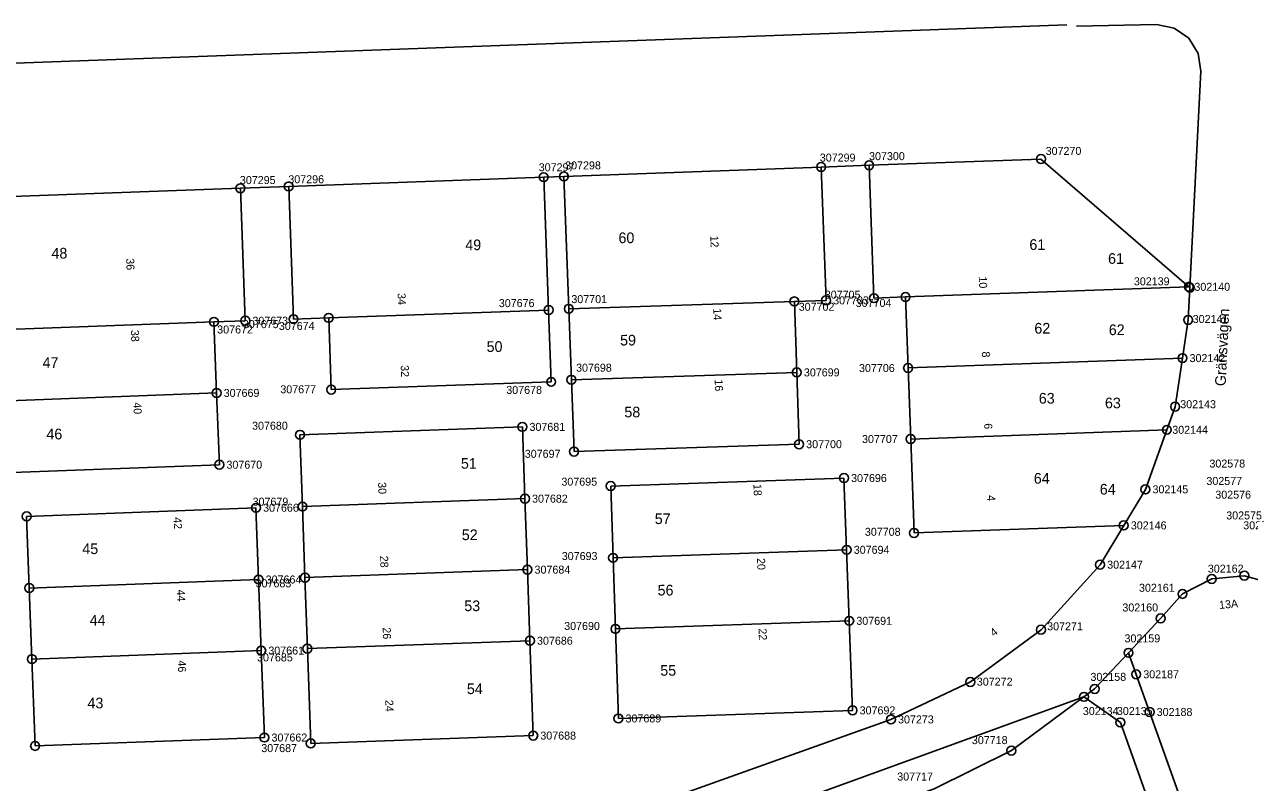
# Model space of a CAD drawing. Extents: x 141995 to 152570, y 6580184 to 6586000.
# Drawn here: x 142748 to 142885.7, y 6585280.8 to 6585366.1 of the extents above; entities that cross this region are included whole.
import ezdxf

# ---------------------------------------------------------------- set-up
doc = ezdxf.new("R2010")
doc.units = 0
for name, color, linetype in [('Level 10', 7, 'Continuous'), ('Level 13', 7, 'Continuous'), ('Level 42', 7, 'Continuous'), ('Level 5', 7, 'Continuous'), ('Level 51', 7, 'Continuous'), ('Level 53', 7, 'Continuous'), ('Level 54', 7, 'Continuous'), ('Level 55', 7, 'Continuous'), ('Level 59', 7, 'Continuous'), ('Level 6', 7, 'Continuous'), ('Level 7', 7, 'Continuous')]:
    doc.layers.add(name, color=color, linetype=linetype)

msp = doc.modelspace()

# ---------------------------------------------------------------- linework, layer by layer
at = {"layer": 'Level 10'}
for centre in [(142837.55, 6585350.09), (142842.95, 6585350.29), (142862.27, 6585350.99), (142806.35, 6585348.95), (142808.62, 6585349.03), (142772.24, 6585347.7), (142777.67, 6585347.9), (142878.9, 6585336.61), (142879.02, 6585336.51), (142834.54, 6585334.96), (142838.1, 6585335.08), (142843.49, 6585335.33), (142847.04, 6585335.46), (142806.9, 6585333.99), (142809.17, 6585334.13), (142769.26, 6585332.66), (142772.79, 6585332.79), (142778.21, 6585332.97), (142782.17, 6585333.11), (142878.83, 6585332.88), (142878.19, 6585328.58), (142834.81, 6585326.97), (142847.33, 6585327.47), (142807.19, 6585325.91), (142809.46, 6585326.14), (142769.56, 6585324.66), (142782.45, 6585325.03), (142877.36, 6585323.11), (142778.94, 6585319.95), (142803.95, 6585320.84), (142876.43, 6585320.51), (142835.07, 6585318.88), (142847.62, 6585319.47), (142809.76, 6585318.06), (142769.87, 6585316.58), (142840.12, 6585315.08), (142813.88, 6585314.18), (142874.02, 6585313.8), (142773.99, 6585311.73), (142779.22, 6585311.87), (142804.24, 6585312.76), (142748.2, 6585310.77), (142848, 6585308.9), (142871.58, 6585309.75), (142814.15, 6585306.1), (142840.42, 6585307), (142804.52, 6585304.77), (142868.92, 6585305.33), (142774.28, 6585303.66), (142779.5, 6585303.87), (142881.48, 6585303.72), (142885.15, 6585304.09), (142748.49, 6585302.7), (142878.19, 6585302.04), (142875.73, 6585299.28), (142814.42, 6585298.1), (142840.71, 6585299.01), (142862.28, 6585298.01), (142804.8, 6585296.77), (142774.58, 6585295.66), (142779.77, 6585295.88), (142872.12, 6585295.41), (142748.79, 6585294.7), (142872.98, 6585292.98), (142854.33, 6585292.13), (142868.31, 6585291.34), (142867.11, 6585290.45), (142841.08, 6585288.93), (142874.49, 6585288.75), (142814.75, 6585288.02), (142845.4, 6585287.91), (142871.2, 6585287.57), (142774.94, 6585285.87), (142805.17, 6585286.09), (142749.15, 6585284.93), (142780.15, 6585285.21), (142858.95, 6585284.4)]:
    msp.add_circle(centre, 0.5, dxfattribs=at)
at = {"layer": 'Level 13'}
for points in [[(142615.3, 6585356.97), (142865.18, 6585366.11)], [(142875.25, 6585366.13), (142866.26, 6585365.96)], [(142877.27, 6585365.72), (142875.25, 6585366.13)], [(142878.89, 6585364.58), (142877.27, 6585365.72)], [(142879.96, 6585362.86), (142878.89, 6585364.58)], [(142880.27, 6585360.89), (142879.96, 6585362.86)], [(142879.02, 6585336.51), (142880.27, 6585360.89)]]:
    msp.add_lwpolyline(points, dxfattribs=at)
at = {"layer": 'Level 5'}
for points in [[(142842.95, 6585350.29), (142862.27, 6585350.99)], [(142862.27, 6585350.99), (142878.9, 6585336.61)], [(142808.62, 6585349.03), (142837.55, 6585350.09)], [(142837.55, 6585350.09), (142842.95, 6585350.29)], [(142772.24, 6585347.7), (142777.67, 6585347.9)], [(142777.67, 6585347.9), (142806.35, 6585348.95)], [(142806.35, 6585348.95), (142808.62, 6585349.03)], [(142742.4, 6585346.61), (142772.24, 6585347.7)], [(142879.02, 6585336.51), (142878.83, 6585332.88)], [(142878.9, 6585336.61), (142879.02, 6585336.51)], [(142878.83, 6585332.88), (142878.19, 6585328.58)], [(142878.19, 6585328.58), (142877.36, 6585323.11)], [(142877.36, 6585323.11), (142876.43, 6585320.51)], [(142876.43, 6585320.51), (142874.02, 6585313.8)], [(142874.02, 6585313.8), (142871.58, 6585309.75)], [(142871.58, 6585309.75), (142868.92, 6585305.33)], [(142862.28, 6585298.01), (142868.92, 6585305.33)], [(142878.19, 6585302.04), (142881.48, 6585303.72)], [(142881.48, 6585303.72), (142885.15, 6585304.09)], [(142885.15, 6585304.09), (142888.7, 6585303.11)], [(142875.73, 6585299.28), (142878.19, 6585302.04)], [(142872.12, 6585295.41), (142875.73, 6585299.28)], [(142862.28, 6585298.01), (142854.33, 6585292.13)], [(142868.31, 6585291.34), (142872.12, 6585295.41)], [(142854.33, 6585292.13), (142845.4, 6585287.91)], [(142867.11, 6585290.45), (142868.31, 6585291.34)], [(142788.63, 6585261.93), (142867.11, 6585290.45)], [(142858.95, 6585284.4), (142867.11, 6585290.45)], [(142845.4, 6585287.91), (142630.63, 6585211.17)], [(142850.27, 6585280.1), (142858.95, 6585284.4)]]:
    msp.add_lwpolyline(points, dxfattribs=at)
at = {"layer": 'Level 6'}
for points in [[(142630.63, 6585211.17), (142845.4, 6585287.91), (142854.33, 6585292.13), (142862.28, 6585298.01), (142868.92, 6585305.33), (142871.58, 6585309.75), (142874.02, 6585313.8), (142876.43, 6585320.51), (142877.36, 6585323.11), (142878.19, 6585328.58), (142878.83, 6585332.88), (142879.02, 6585336.51), (142878.9, 6585336.61), (142862.27, 6585350.99), (142842.95, 6585350.29), (142837.55, 6585350.09), (142808.62, 6585349.03), (142806.35, 6585348.95), (142777.67, 6585347.9), (142772.24, 6585347.7), (142742.4, 6585346.61)], [(142888.7, 6585303.11), (142885.15, 6585304.09), (142881.48, 6585303.72), (142878.19, 6585302.04), (142875.73, 6585299.28), (142872.12, 6585295.41), (142868.31, 6585291.34), (142867.11, 6585290.45), (142858.95, 6585284.4), (142850.27, 6585280.1), (142826.03, 6585271.43), (142822.74, 6585270.26), (142801.83, 6585262.78), (142783.27, 6585256.15), (142780.72, 6585254.66), (142778.89, 6585252.36), (142778.01, 6585249.55), (142778.21, 6585246.61), (142785.15, 6585219.83)]]:
    msp.add_lwpolyline(points, dxfattribs=at)
at = {"layer": 'Level 7'}
for points in [[(142837.55, 6585350.09), (142838.1, 6585335.08)], [(142843.49, 6585335.33), (142842.95, 6585350.29)], [(142778.21, 6585332.97), (142777.67, 6585347.9)], [(142806.35, 6585348.95), (142806.9, 6585333.99)], [(142809.17, 6585334.13), (142808.62, 6585349.03)], [(142772.24, 6585347.7), (142772.79, 6585332.79)], [(142847.04, 6585335.46), (142843.49, 6585335.33)], [(142847.04, 6585335.46), (142878.9, 6585336.61)], [(142847.33, 6585327.47), (142847.04, 6585335.46)], [(142809.17, 6585334.13), (142834.54, 6585334.96)], [(142809.46, 6585326.14), (142809.17, 6585334.13)], [(142838.1, 6585335.08), (142834.54, 6585334.96)], [(142834.54, 6585334.96), (142834.81, 6585326.97)], [(142742.95, 6585331.67), (142769.26, 6585332.66)], [(142772.79, 6585332.79), (142769.26, 6585332.66)], [(142769.26, 6585332.66), (142769.56, 6585324.66)], [(142782.17, 6585333.11), (142778.21, 6585332.97)], [(142806.9, 6585333.99), (142782.17, 6585333.11)], [(142782.45, 6585325.03), (142782.17, 6585333.11)], [(142806.9, 6585333.99), (142807.19, 6585325.91)], [(142847.33, 6585327.47), (142878.19, 6585328.58)], [(142847.62, 6585319.47), (142847.33, 6585327.47)], [(142807.19, 6585325.91), (142782.45, 6585325.03)], [(142809.46, 6585326.14), (142834.81, 6585326.97)], [(142809.76, 6585318.06), (142809.46, 6585326.14)], [(142834.81, 6585326.97), (142835.07, 6585318.88)], [(142743.24, 6585323.67), (142769.56, 6585324.66)], [(142769.56, 6585324.66), (142769.87, 6585316.58)], [(142778.94, 6585319.95), (142803.95, 6585320.84)], [(142803.95, 6585320.84), (142804.24, 6585312.76)], [(142847.62, 6585319.47), (142876.43, 6585320.51)], [(142779.22, 6585311.87), (142778.94, 6585319.95)], [(142835.07, 6585318.88), (142809.76, 6585318.06)], [(142848, 6585308.9), (142847.62, 6585319.47)], [(142769.87, 6585316.58), (142743.54, 6585315.59)], [(142813.88, 6585314.18), (142840.12, 6585315.08)], [(142840.12, 6585315.08), (142840.42, 6585307)], [(142814.15, 6585306.1), (142813.88, 6585314.18)], [(142804.24, 6585312.76), (142779.22, 6585311.87)], [(142804.24, 6585312.76), (142804.52, 6585304.77)], [(142748.2, 6585310.77), (142773.99, 6585311.73)], [(142748.49, 6585302.7), (142748.2, 6585310.77)], [(142773.99, 6585311.73), (142774.28, 6585303.66)], [(142779.5, 6585303.87), (142779.22, 6585311.87)], [(142848, 6585308.9), (142871.58, 6585309.75)], [(142814.15, 6585306.1), (142840.42, 6585307)], [(142840.42, 6585307), (142840.71, 6585299.01)], [(142814.42, 6585298.1), (142814.15, 6585306.1)], [(142804.52, 6585304.77), (142779.5, 6585303.87)], [(142779.77, 6585295.88), (142779.5, 6585303.87)], [(142804.52, 6585304.77), (142804.8, 6585296.77)], [(142748.49, 6585302.7), (142774.28, 6585303.66)], [(142748.79, 6585294.7), (142748.49, 6585302.7)], [(142774.28, 6585303.66), (142774.58, 6585295.66)], [(142814.42, 6585298.1), (142840.71, 6585299.01)], [(142840.71, 6585299.01), (142841.08, 6585288.93)], [(142814.75, 6585288.02), (142814.42, 6585298.1)], [(142748.79, 6585294.7), (142774.58, 6585295.66)], [(142774.58, 6585295.66), (142774.94, 6585285.87)], [(142804.8, 6585296.77), (142779.77, 6585295.88)], [(142780.15, 6585285.21), (142779.77, 6585295.88)], [(142804.8, 6585296.77), (142805.17, 6585286.09)], [(142749.15, 6585284.93), (142748.79, 6585294.7)], [(142872.12, 6585295.41), (142872.98, 6585292.98)], [(142872.98, 6585292.98), (142874.49, 6585288.75)], [(142867.11, 6585290.45), (142871.2, 6585287.57)], [(142841.08, 6585288.93), (142814.75, 6585288.02)], [(142874.49, 6585288.75), (142883.23, 6585264.26)], [(142871.2, 6585287.57), (142880.89, 6585260.38)], [(142774.94, 6585285.87), (142749.15, 6585284.93)], [(142805.17, 6585286.09), (142780.15, 6585285.21)]]:
    msp.add_lwpolyline(points, dxfattribs=at)

# ---------------------------------------------------------------- texts
at = {"layer": 'Level 42'}
msp.add_text('Gränsvägen', height=1.2, rotation=87.285, dxfattribs=at).set_placement((142883.04, 6585325.4))
at = {"layer": 'Level 51'}
for s, rotation, p in [('60', 0.0493, (142814.76, 6585341.52)), ('48', 0.0493, (142750.99, 6585339.79)), ('49', 0.0493, (142797.53, 6585340.73)), ('61', 0.0493, (142860.97, 6585340.76)), ('62', 0.0493, (142861.53, 6585331.34)), ('50', 0.0493, (142799.93, 6585329.28)), ('59', 0.0493, (142814.94, 6585330)), ('47', 0.0493, (142749.99, 6585327.47)), ('63', 0.0493, (142862.03, 6585323.46)), ('58', 0.0493, (142815.42, 6585321.91)), ('46', 0.0493, (142750.42, 6585319.43)), ('51', 0.0493, (142797.04, 6585316.13)), ('64', 0.0493, (142861.47, 6585314.45)), ('57', 0.0493, (142818.84, 6585309.9)), ('52', 0.0493, (142797.14, 6585308.09)), ('45', 0.0493, (142754.46, 6585306.52)), ('56', 0.0493, (142819.16, 6585301.86)), ('53', 0.0493, (142797.42, 6585300.1)), ('44', 0.0493, (142755.29, 6585298.48)), ('55', 0.0493, (142819.46, 6585292.83)), ('54', 0.0493, (142797.71, 6585290.76)), ('43', 0.0514, (142755.04, 6585289.16))]:
    msp.add_text(s, height=1.2, rotation=rotation, dxfattribs=at).set_placement(p)
at = {"layer": 'Level 53'}
for s, p in [('307270', (142862.8, 6585351.45)), ('307298', (142808.76, 6585349.82)), ('307299', (142837.4, 6585350.7)), ('307300', (142842.94, 6585350.86)), ('307296', (142777.63, 6585348.26)), ('307297', (142805.79, 6585349.61)), ('307295', (142772.18, 6585348.17)), ('302139', (142872.72, 6585336.77)), ('302140', (142879.53, 6585336.16)), ('307701', (142809.46, 6585334.77)), ('307705', (142837.96, 6585335.27)), ('307703', (142838.9, 6585334.63)), ('307676', (142801.3, 6585334.32)), ('307702', (142835.03, 6585333.91)), ('307704', (142841.44, 6585334.34)), ('307675', (142772.52, 6585331.95)), ('307673', (142773.59, 6585332.34)), ('307674', (142776.56, 6585331.75)), ('302141', (142879.34, 6585332.53)), ('307672', (142769.63, 6585331.35)), ('302142', (142878.99, 6585328.13)), ('307698', (142809.99, 6585327.05)), ('307699', (142835.61, 6585326.52)), ('307706', (142841.81, 6585327.01)), ('307669', (142770.36, 6585324.21)), ('307677', (142776.73, 6585324.62)), ('307678', (142802.14, 6585324.55)), ('302143', (142877.94, 6585322.94)), ('307680', (142773.55, 6585320.52)), ('307681', (142804.75, 6585320.39)), ('302144', (142877.04, 6585320.06)), ('307700', (142835.87, 6585318.44)), ('307707', (142842.15, 6585319.02)), ('307697', (142804.22, 6585317.36)), ('307670', (142770.67, 6585316.13)), ('302578', (142881.22, 6585316.26)), ('307695', (142808.34, 6585314.22)), ('307696', (142840.92, 6585314.63)), ('302577', (142880.88, 6585314.3)), ('302145', (142874.82, 6585313.36)), ('302576', (142881.88, 6585312.76)), ('307679', (142773.61, 6585311.97)), ('307666', (142774.79, 6585311.29)), ('307682', (142805.04, 6585312.31)), ('302575', (142883.11, 6585310.42)), ('307708', (142842.47, 6585308.58)), ('302146', (142872.38, 6585309.3)), ('302574', (142885.02, 6585309.31)), ('307693', (142808.38, 6585305.85)), ('307694', (142841.22, 6585306.55)), ('307684', (142805.32, 6585304.32)), ('302147', (142869.72, 6585304.88)), ('302162', (142881.04, 6585304.43)), ('307664', (142775.08, 6585303.21)), ('307683', (142773.95, 6585302.78)), ('302161', (142873.3, 6585302.28)), ('302160', (142871.43, 6585300.06)), ('307690', (142808.65, 6585297.98)), ('307691', (142841.51, 6585298.56)), ('307271', (142862.97, 6585297.94)), ('307686', (142805.6, 6585296.32)), ('302159', (142871.67, 6585296.58)), ('307661', (142775.38, 6585295.21)), ('307685', (142774.11, 6585294.44)), ('302158', (142867.84, 6585292.25)), ('302187', (142873.78, 6585292.54)), ('307272', (142855.06, 6585291.71)), ('307692', (142841.88, 6585288.48)), ('302134', (142866.98, 6585288.4)), ('302135', (142870.81, 6585288.41)), ('302188', (142875.29, 6585288.3)), ('307689', (142815.55, 6585287.57)), ('307273', (142846.2, 6585287.46)), ('307662', (142775.74, 6585285.42)), ('307688', (142805.97, 6585285.64)), ('307718', (142854.5, 6585285.13)), ('307687', (142774.59, 6585284.23)), ('307717', (142846.11, 6585281.03))]:
    msp.add_text(s, height=0.9, rotation=0.0493, dxfattribs=at).set_placement(p)
at = {"layer": 'Level 54'}
for s, rotation, p in [('12', 272.098, (142825.08, 6585342.35)), ('36', 272.1, (142759.39, 6585339.8)), ('10', 272.098, (142855.28, 6585337.76)), ('34', 272.097, (142789.91, 6585335.89)), ('14', 271.872, (142825.41, 6585334.18)), ('38', 272.166, (142759.92, 6585331.74)), ('8', 272.073, (142855.64, 6585329.31)), ('32', 272.045, (142790.27, 6585327.77)), ('16', 271.867, (142825.58, 6585326.17)), ('40', 272.164, (142760.2, 6585323.59)), ('6', 272.073, (142855.89, 6585321.23)), ('30', 271.995, (142787.72, 6585314.6)), ('18', 272.101, (142829.93, 6585314.4)), ('4', 272.067, (142856.23, 6585313.14)), ('42', 272.108, (142764.73, 6585310.66)), ('28', 271.994, (142787.95, 6585306.32)), ('20', 272.109, (142830.34, 6585306.06)), ('44', 272.11, (142765.09, 6585302.51)), ('26', 271.994, (142788.24, 6585298.26)), ('22', 272.098, (142830.51, 6585298.14)), ('46', 272.111, (142765.19, 6585294.54)), ('24', 271.996, (142788.52, 6585290.1))]:
    msp.add_text(s, height=0.9, rotation=rotation, dxfattribs=at).set_placement(p)
at = {"layer": 'Level 55'}
for s, rotation, p in [('13A', 5.0493, (142882.34, 6585300.34)), ('4', 36.5386, (142856.97, 6585297.19))]:
    msp.add_text(s, height=0.9, rotation=rotation, dxfattribs=at).set_placement(p)
at = {"layer": 'Level 59'}
for s, p in [('61', (142869.82, 6585339.19)), ('62', (142869.9, 6585331.17)), ('63', (142869.47, 6585322.93)), ('64', (142868.89, 6585313.22))]:
    msp.add_text(s, height=1.2, rotation=0.0493, dxfattribs=at).set_placement(p)

doc.saveas('drawing.dxf')
